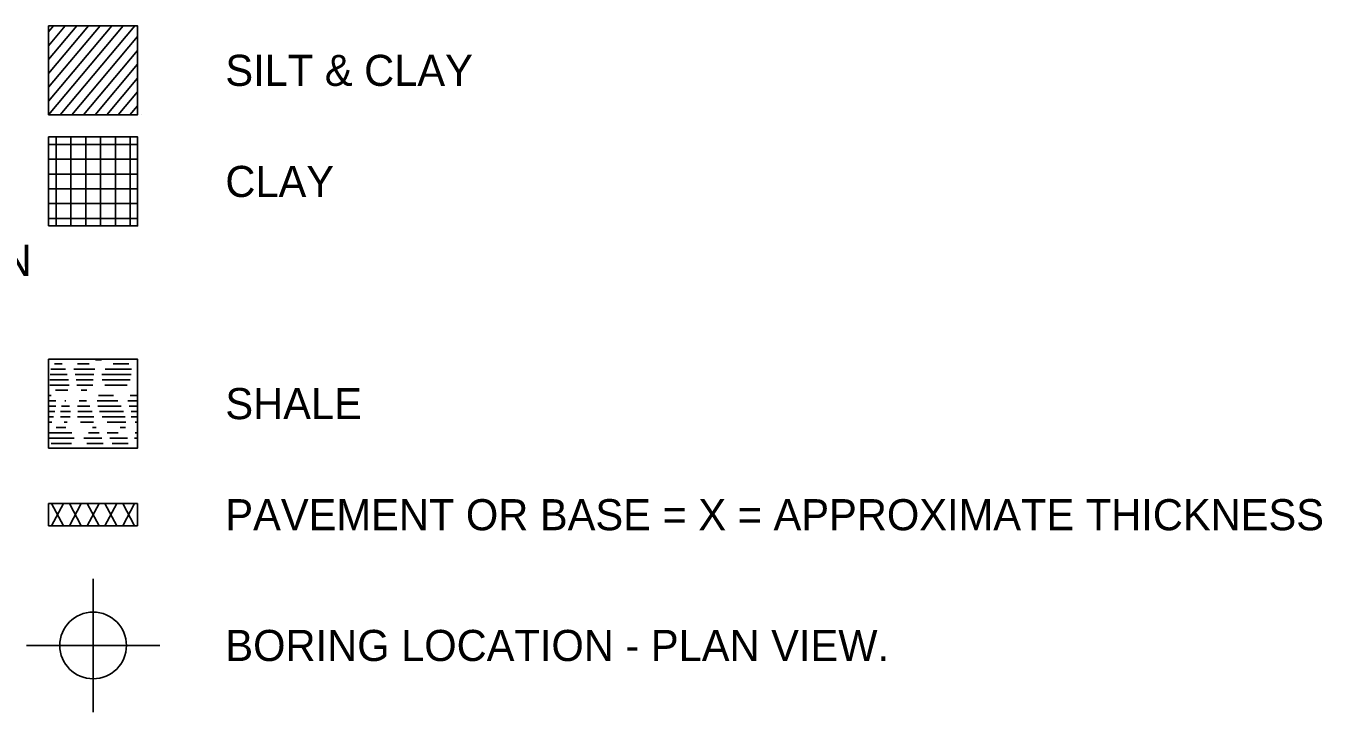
# Model space of a CAD drawing. Extents: x 0 to 34, y 0 to 22.
# Drawn here: x 11.81 to 17.64, y 15.83 to 18.91 of the extents above; entities that cross this region are included whole.
import ezdxf

# ---------------------------------------------------------------- set-up
doc = ezdxf.new("R2010")
doc.units = 0
for name, color, linetype in [('GT_Project_Soil_Boring', 7, 'Continuous'), ('GT_Project_Soil_Layers', 7, 'Continuous'), ('SH_Data', 7, 'Continuous'), ('SH_Text', 7, 'Continuous')]:
    doc.layers.add(name, color=color, linetype=linetype)

msp = doc.modelspace()

# ---------------------------------------------------------------- linework, layer by layer
at = {"layer": 'GT_Project_Soil_Boring'}
for p, q in [((12.1166, 16.1265), (12.1166, 16.4265)), ((12.1166, 16.2765), (12.1166, 16.1265)), ((12.1166, 16.1265), (11.8166, 16.1265)), ((12.1166, 16.1265), (11.9666, 16.1265)), ((12.1166, 16.1265), (12.1166, 15.8265)), ((12.1166, 16.1265), (12.4166, 16.1265)), ((12.1166, 15.9765), (12.1166, 16.1265)), ((12.1166, 16.1265), (12.2666, 16.1265))]:
    msp.add_line(p, q, dxfattribs=at)
msp.add_circle((12.1166, 16.1265), 0.15, dxfattribs=at)
for start, end in [(90, 180), (270, 360)]:
    msp.add_arc((12.1166, 16.1265), 0.15, start, end, dxfattribs=at)
at = {"layer": 'GT_Project_Soil_Layers'}
for p, q in [((11.9299, 16.7649), (11.9833, 16.665)), ((11.9299, 16.665), (11.9833, 16.7649)), ((12.0099, 16.665), (12.0633, 16.7649)), ((12.0099, 16.7649), (12.0633, 16.665)), ((12.0899, 16.7649), (12.1433, 16.665)), ((12.0899, 16.665), (12.1433, 16.7649)), ((12.1699, 16.7649), (12.2233, 16.665)), ((12.1699, 16.665), (12.2233, 16.7649)), ((12.2499, 16.7649), (12.3033, 16.665)), ((12.2499, 16.665), (12.3033, 16.7649))]:
    msp.add_line(p, q, dxfattribs=at)
at = {"layer": 'SH_Data'}
for p, q in [((11.9166, 16.665), (11.9166, 16.7649)), ((11.9166, 16.7649), (12.3166, 16.7649)), ((12.3166, 16.665), (12.3166, 16.7649)), ((11.9166, 16.665), (12.3166, 16.665))]:
    msp.add_line(p, q, dxfattribs=at)
for points in [[(11.9167, 18.515), (12.3167, 18.515), (12.3167, 18.915), (11.9167, 18.915)], [(11.9167, 18.015), (12.3167, 18.015), (12.3167, 18.415), (11.9167, 18.415)], [(11.9167, 17.015), (12.3167, 17.015), (12.3167, 17.415), (11.9167, 17.415)]]:
    msp.add_lwpolyline(points, close=True, dxfattribs=at)
at = {"layer": 'SH_Text'}
for p, q in [((11.9165, 18.8259), (11.9913, 18.915)), ((11.9165, 18.7637), (12.0435, 18.915)), ((11.9165, 18.7015), (12.0957, 18.915)), ((11.9165, 18.6393), (12.148, 18.915)), ((11.9165, 18.577), (12.2002, 18.915)), ((11.9167, 18.515), (12.2524, 18.915)), ((11.9167, 18.8883), (11.9391, 18.915)), ((11.9689, 18.515), (12.3046, 18.915)), ((12.0211, 18.515), (12.3167, 18.8671)), ((12.0733, 18.515), (12.3167, 18.8049)), ((12.1256, 18.515), (12.3167, 18.7427)), ((12.1778, 18.515), (12.3167, 18.6805)), ((12.23, 18.515), (12.3167, 18.6182)), ((12.2822, 18.515), (12.3167, 18.556)), ((11.9167, 18.515), (11.9167, 18.515)), ((12.3343, 18.515), (12.3343, 18.515)), ((11.9167, 18.415), (11.9167, 18.415)), ((11.9167, 18.3816), (12.3167, 18.3816)), ((11.95, 18.015), (11.95, 18.415)), ((12.0167, 18.015), (12.0167, 18.415)), ((12.0834, 18.015), (12.0834, 18.415)), ((12.15, 18.015), (12.15, 18.415)), ((12.2167, 18.015), (12.2167, 18.415)), ((12.2834, 18.015), (12.2834, 18.415)), ((12.3167, 18.415), (12.3167, 18.415)), ((11.9167, 18.315), (12.3167, 18.315)), ((11.9167, 18.2483), (12.3167, 18.2483)), ((11.9167, 18.1816), (12.3167, 18.1816)), ((11.9167, 18.115), (12.3167, 18.115)), ((11.9167, 18.0483), (12.3167, 18.0483)), ((11.9167, 18.015), (11.9167, 18.015)), ((12.3167, 18.015), (12.3167, 18.015)), ((11.9167, 17.415), (11.9167, 17.415)), ((11.9779, 17.3943), (11.9427, 17.3943)), ((12.0984, 17.3943), (12.046, 17.3943)), ((12.1546, 17.4119), (12.128, 17.4119)), ((12.2778, 17.3943), (12.2065, 17.3943)), ((12.3167, 17.415), (12.3167, 17.415)), ((12.006, 17.3226), (11.9214, 17.3226)), ((12.0002, 17.3465), (11.9242, 17.3465)), ((11.9931, 17.3704), (11.9265, 17.3704)), ((12.124, 17.3704), (12.0297, 17.3704)), ((12.1207, 17.3465), (12.0359, 17.3465)), ((12.1173, 17.3226), (12.0411, 17.3226)), ((12.2885, 17.3465), (12.156, 17.3465)), ((12.2838, 17.3226), (12.1568, 17.3226)), ((12.2893, 17.3704), (12.1702, 17.3704)), ((12.0094, 17.2987), (11.9217, 17.2987)), ((12.0031, 17.2748), (11.9471, 17.2748)), ((12.1159, 17.2987), (12.043, 17.2987)), ((12.0884, 17.2748), (12.063, 17.2748)), ((12.2704, 17.2987), (12.1699, 17.2987)), ((11.9276, 17.2509), (11.9167, 17.2509)), ((11.9486, 17.227), (11.9167, 17.227)), ((11.949, 17.2031), (11.9167, 17.2031)), ((12.011, 17.2031), (11.9752, 17.2031)), ((11.994, 17.227), (11.9898, 17.227)), ((12.1023, 17.2031), (12.046, 17.2031)), ((12.0876, 17.227), (12.0541, 17.227)), ((12.228, 17.227), (12.1343, 17.227)), ((12.2428, 17.2031), (12.1383, 17.2031)), ((12.2089, 17.2509), (12.1412, 17.2509)), ((12.3167, 17.227), (12.2732, 17.227)), ((12.3167, 17.2031), (12.2789, 17.2031)), ((12.3167, 17.2509), (12.2838, 17.2509)), ((11.9441, 17.1792), (11.9167, 17.1792)), ((11.9391, 17.1553), (11.9167, 17.1553)), ((12.0157, 17.1792), (11.9694, 17.1792)), ((12.0139, 17.1553), (11.9699, 17.1553)), ((12.1201, 17.1553), (12.0465, 17.1553)), ((12.1129, 17.1792), (12.0473, 17.1792)), ((12.2534, 17.1792), (12.1455, 17.1792)), ((12.2604, 17.1553), (12.1576, 17.1553)), ((12.3167, 17.1792), (12.2877, 17.1792)), ((12.3167, 17.1553), (12.2878, 17.1553)), ((11.9309, 17.1314), (11.9167, 17.1314)), ((12.0203, 17.0836), (11.9167, 17.0836)), ((11.9935, 17.1075), (11.9498, 17.1075)), ((12.0003, 17.1314), (11.9867, 17.1314)), ((12.1188, 17.1314), (12.0601, 17.1314)), ((12.1439, 17.0836), (12.0961, 17.0836)), ((12.1308, 17.1075), (12.1134, 17.1075)), ((12.2644, 17.1314), (12.1797, 17.1314)), ((12.2289, 17.0836), (12.1803, 17.0836)), ((12.2621, 17.1075), (12.2382, 17.1075)), ((12.3167, 17.1314), (12.3054, 17.1314)), ((12.3063, 17.0836), (12.3167, 17.0836)), ((12.0322, 17.0597), (11.9167, 17.0597)), ((12.0188, 17.0358), (11.9281, 17.0358)), ((12.1555, 17.0597), (12.0757, 17.0597)), ((12.1617, 17.0358), (12.0882, 17.0358)), ((12.2717, 17.0597), (12.1913, 17.0597)), ((12.2744, 17.0358), (12.2029, 17.0358)), ((12.3034, 17.0597), (12.3167, 17.0597)), ((11.9167, 17.015), (11.9167, 17.015)), ((12.3167, 17.015), (12.3167, 17.015))]:
    msp.add_line(p, q, dxfattribs=at)

# ---------------------------------------------------------------- texts
for s, p in [('SILT & CLAY', (12.7116, 18.645)), ('CLAY', (12.7116, 18.145)), ('HILLS AND RIDGES WITH INTERVENING VALLEYS. THE PROJECT SITE IS LOCATED IN THE NORTHWESTERN ', (2, 17.79)), ('SHALE', (12.7116, 17.145)), ('PAVEMENT OR BASE = X = APPROXIMATE THICKNESS', (12.7116, 16.645)), ('BORING LOCATION - PLAN VIEW.', (12.7116, 16.0565))]:
    msp.add_text(s, height=0.14, dxfattribs=at).set_placement(p)

doc.saveas('drawing.dxf')
